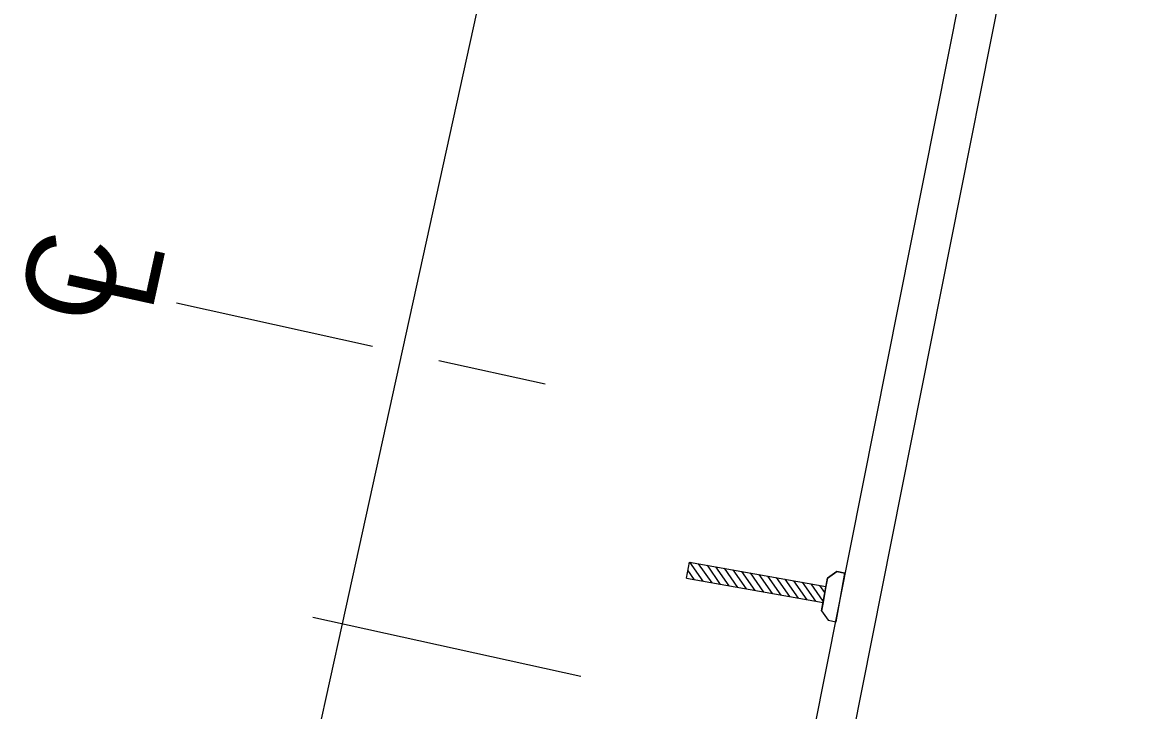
# Model space of a CAD drawing. Extents: x 14104283 to 14120882, y 8635219 to 8671666.
# Drawn here: x 14107411.4 to 14107513.2, y 8639321 to 8639383.1 of the extents above; entities that cross this region are included whole.
import ezdxf

# ---------------------------------------------------------------- set-up
doc = ezdxf.new("R2010")
doc.units = 0
for name, color, linetype in [('Cell', 7, 'Continuous'), ('dsnTextFinalPlan', 7, 'Continuous'), ('TC_SubstrataExistingPavement', 7, 'Continuous'), ('Terrain', 7, 'Continuous')]:
    doc.layers.add(name, color=color, linetype=linetype)

msp = doc.modelspace()

# ---------------------------------------------------------------- linework, layer by layer
at = {"layer": 'Cell'}
for p, q in [((14107471.34, 8639332.93), (14107471.6, 8639334.39)), ((14107471.6, 8639334.39), (14107483.93, 8639332.2)), ((14107472.85, 8639332.66), (14107471.65, 8639334.38)), ((14107473.64, 8639332.52), (14107472.43, 8639334.24)), ((14107474.42, 8639332.38), (14107473.22, 8639334.11)), ((14107475.2, 8639332.24), (14107474, 8639333.97)), ((14107471.34, 8639332.93), (14107483.67, 8639330.73)), ((14107472.07, 8639332.8), (14107471.47, 8639333.67)), ((14107475.98, 8639332.1), (14107474.78, 8639333.83)), ((14107476.76, 8639331.97), (14107475.56, 8639333.69)), ((14107477.54, 8639331.83), (14107476.34, 8639333.55)), ((14107478.33, 8639331.69), (14107477.13, 8639333.41)), ((14107479.11, 8639331.55), (14107477.91, 8639333.27)), ((14107479.89, 8639331.41), (14107478.69, 8639333.13)), ((14107480.67, 8639331.27), (14107479.47, 8639332.99)), ((14107481.45, 8639331.13), (14107480.25, 8639332.85)), ((14107483.54, 8639330), (14107484.06, 8639332.93)), ((14107484.06, 8639332.93), (14107483.93, 8639332.2)), ((14107484.92, 8639333.53), (14107484.06, 8639332.93)), ((14107484.06, 8639332.93), (14107484.92, 8639333.53)), ((14107484.86, 8639329.01), (14107485.64, 8639333.4)), ((14107484.86, 8639329.01), (14107485.64, 8639333.4)), ((14107485.64, 8639333.4), (14107484.92, 8639333.53)), ((14107484.92, 8639333.53), (14107485.64, 8639333.4)), ((14107482.24, 8639330.99), (14107481.03, 8639332.71)), ((14107483.02, 8639330.85), (14107481.82, 8639332.57)), ((14107483.69, 8639330.86), (14107482.6, 8639332.43)), ((14107483.83, 8639331.65), (14107483.38, 8639332.29)), ((14107483.93, 8639332.2), (14107483.67, 8639330.73)), ((14107483.67, 8639330.73), (14107483.54, 8639330)), ((14107483.54, 8639330), (14107484.14, 8639329.14)), ((14107483.54, 8639330), (14107484.14, 8639329.14)), ((14107484.14, 8639329.14), (14107484.86, 8639329.01)), ((14107484.14, 8639329.14), (14107484.86, 8639329.01))]:
    msp.add_line(p, q, dxfattribs=at)
at = {"layer": 'dsnTextFinalPlan'}
for p, q in [((14107440.25, 8639328.81), (14107469.11, 8639460.14)), ((14107425.26, 8639357.8), (14107442.97, 8639353.91)), ((14107448.95, 8639352.6), (14107458.56, 8639350.49)), ((14107429.95, 8639281.93), (14107440.25, 8639328.81)), ((14107461.8, 8639324.07), (14107437.58, 8639329.39))]:
    msp.add_line(p, q, dxfattribs=at)
at = {"layer": 'TC_SubstrataExistingPavement'}
msp.add_lwpolyline([(14107513.16, 8639450.46), (14107500.59, 8639390.4), (14107481.87, 8639296.22), (14107478.45, 8639296.97)], dxfattribs=at)
at = {"layer": 'Terrain'}
msp.add_lwpolyline([(14107471.43, 8639257.56), (14107478.45, 8639296.97), (14107497.18, 8639391.15), (14107509.74, 8639451.21)], dxfattribs=at)

# ---------------------------------------------------------------- texts
at = {"layer": 'dsnTextFinalPlan'}
for s, p in [('C', (14107418.76, 8639355.52)), ('L', (14107423.01, 8639356.83))]:
    msp.add_text(s, height=8, rotation=77.6078, dxfattribs=at).set_placement(p)

doc.saveas('drawing.dxf')
